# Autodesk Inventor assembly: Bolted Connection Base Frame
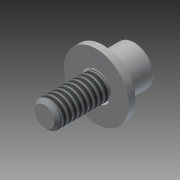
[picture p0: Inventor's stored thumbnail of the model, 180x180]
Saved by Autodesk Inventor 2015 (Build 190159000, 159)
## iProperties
Created: 2007-02
Part Number: Bolted Connection Base Frame
Document SubType Name: Assembly
Designer: Autodesk, Inc.
Mass: 10.0071 g
Surface Area: 14.1283 cm^2
Volume: 1.27317 cm^3
Density: 7.86 g/cm^3
ClientObjectVersion: 1
Author: Autodesk, Inc.
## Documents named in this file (4)
- C:\Users\Public\Documents\Autodesk\Inventor 2015\Samples\Models\Assemblies\Blower\Blower\Design Accelerator\Bolted Connection Exhaust Housing1.iam
- C:\Users\Public\Documents\Autodesk\Inventor 2015\Samples\Standard Parts\en-US\ANSI B18.22.1\ANSI B18.22.1 - 1_4 - narrow - Type A.ipt
- C:\Users\Public\Documents\Autodesk\Inventor 2015\Samples\Standard Parts\en-US\ANSI B18.21.1\ANSI B18.21.1 - 0.25.ipt
- C:\Users\Public\Documents\Autodesk\Inventor 2015\Samples\Standard Parts\en-US\ANSI B18.3(13)\ANSI B18.3 - 1_4-20 UNC - 0.625(22).ipt
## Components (3 placed, 3 different names)
1. ANSI B18.22.1 - 1/4 - narrow - Type A:1
2. ANSI B18.21.1 - 0.25:2
3. ANSI B18.3 - 1/4-20 UNC - 0.625:3
